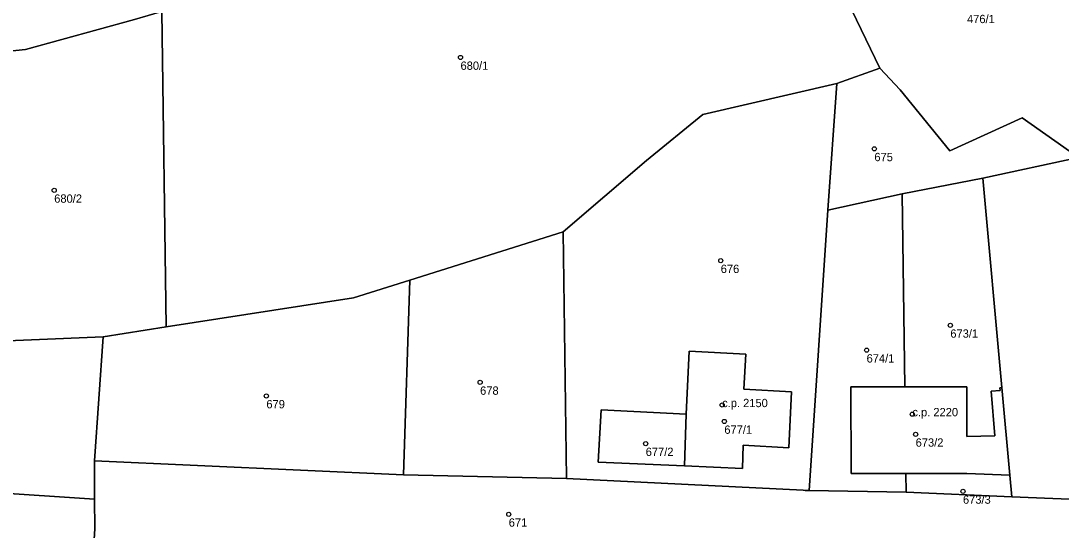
# Model space of a CAD drawing. Extents: x -878211 to -870363, y -1058464 to -1052522.
# Drawn here: x -874523.6 to -874398.3, y -1056486.9 to -1056425.6 of the extents above; entities that cross this region are included whole.
import ezdxf

# ---------------------------------------------------------------- set-up
doc = ezdxf.new("R2010")
doc.units = 0
for name, color, linetype in [('Definiční body', 7, 'Continuous'), ('Polygon budovy', 7, 'Continuous'), ('Polygon parcely', 7, 'Continuous')]:
    doc.layers.add(name, color=color, linetype=linetype)

msp = doc.modelspace()

# ---------------------------------------------------------------- linework, layer by layer
at = {"layer": 'Definiční body'}
for centre in [(-874470.63, -1056429.99994), (-874420.77, -1056440.99994), (-874519.58, -1056445.99994), (-874439.28, -1056454.45994), (-874411.62, -1056462.24994), (-874421.71, -1056465.23994), (-874468.27, -1056469.11994), (-874494.02, -1056470.74994), (-874439.11, -1056471.84994), (-874438.85, -1056473.81994), (-874416.19, -1056472.94994), (-874415.8, -1056475.36994), (-874448.32, -1056476.48994), (-874410.1, -1056482.23994), (-874464.82, -1056484.99994)]:
    msp.add_circle(centre, 0.25, dxfattribs=at)
at = {"layer": 'Polygon budovy'}
for points in [[(-874443.66, -1056479.17), (-874436.67, -1056479.47), (-874436.57, -1056476.69), (-874431.07, -1056476.98), (-874430.76, -1056470.25), (-874436.48, -1056469.95), (-874436.27, -1056465.74), (-874443.07, -1056465.36), (-874443.46, -1056472.94)], [(-874417.11, -1056469.65), (-874423.59, -1056469.65), (-874423.57, -1056480.1), (-874416.97, -1056480.09), (-874409.63, -1056480.07), (-874404.47, -1056480.3), (-874405.42, -1056469.74), (-874405.66, -1056469.79), (-874405.61, -1056470.08), (-874406.72, -1056470.18), (-874406.25, -1056475.54), (-874409.64, -1056475.64), (-874409.64, -1056469.65)]]:
    msp.add_lwpolyline(points, close=True, dxfattribs=at)
at = {"layer": 'Polygon parcely'}
for points in [[(-874480.73, -1056416.32), (-874482.07, -1056416.75), (-874490.03, -1056419.45), (-874505.5, -1056424.13), (-874506.63, -1056424.46), (-874506.09, -1056462.44), (-874483.53, -1056458.93), (-874476.75, -1056456.82), (-874458.26, -1056450.98), (-874448.21, -1056442.41), (-874441.44, -1056436.86), (-874425.29, -1056433.14), (-874420.12, -1056431.27), (-874435.23, -1056399.98), (-874439.22, -1056401.77), (-874464.13, -1056411.06)], [(-874506.63, -1056424.46), (-874505.5, -1056424.13), (-874490.03, -1056419.45), (-874482.07, -1056416.75), (-874480.73, -1056416.32), (-874484.53, -1056404.72), (-874506.28, -1056409.52), (-874544.06, -1056414.29), (-874571.8, -1056418.71), (-874569.39, -1056432.89), (-874561.56, -1056432.43), (-874554.89, -1056431.78), (-874547.93, -1056431.29), (-874538.64, -1056430.41), (-874535.46, -1056430.33), (-874523.03, -1056429.03), (-874509.91, -1056425.43)], [(-874509.91, -1056425.43), (-874523.03, -1056429.03), (-874535.46, -1056430.33), (-874537.69, -1056464.65), (-874513.7, -1056463.63), (-874506.09, -1056462.44), (-874506.63, -1056424.46)], [(-874417.41, -1056446.4), (-874407.71, -1056444.55), (-874396.18, -1056442.04), (-874402.98, -1056437.26), (-874411.69, -1056441.25), (-874417.67, -1056433.88), (-874420.12, -1056431.27), (-874425.29, -1056433.14), (-874426.38, -1056448.38)], [(-874457.88, -1056480.71), (-874429.37, -1056482.11), (-874429.12, -1056482.12), (-874428.61, -1056482.15), (-874426.38, -1056448.38), (-874425.29, -1056433.14), (-874441.44, -1056436.86), (-874448.21, -1056442.41), (-874458.26, -1056450.98)], [(-874404.47, -1056480.3), (-874404.23, -1056482.9), (-874370.58, -1056484.27), (-874393, -1056445.85), (-874396.18, -1056442.04), (-874407.71, -1056444.55), (-874405.42, -1056469.74)], [(-874407.71, -1056444.55), (-874417.41, -1056446.4), (-874417.11, -1056469.65), (-874409.64, -1056469.65), (-874409.64, -1056475.64), (-874406.25, -1056475.54), (-874406.72, -1056470.18), (-874405.61, -1056470.08), (-874405.66, -1056469.79), (-874405.42, -1056469.74)], [(-874417.11, -1056469.65), (-874417.41, -1056446.4), (-874426.38, -1056448.38), (-874428.61, -1056482.15), (-874416.94, -1056482.33), (-874416.97, -1056480.09), (-874423.57, -1056480.1), (-874423.59, -1056469.65)], [(-874477.5, -1056480.25), (-874457.88, -1056480.71), (-874458.26, -1056450.98), (-874476.75, -1056456.82)], [(-874514.72, -1056478.57), (-874477.5, -1056480.25), (-874476.75, -1056456.82), (-874483.53, -1056458.93), (-874506.09, -1056462.44), (-874513.7, -1056463.63)], [(-874514.71, -1056483.17), (-874514.72, -1056478.57), (-874513.7, -1056463.63), (-874537.69, -1056464.65), (-874540.74, -1056481.47)], [(-874443.46, -1056472.94), (-874443.07, -1056465.36), (-874436.27, -1056465.74), (-874436.48, -1056469.95), (-874430.76, -1056470.25), (-874431.07, -1056476.98), (-874436.57, -1056476.69), (-874436.67, -1056479.47), (-874443.66, -1056479.17), (-874454.05, -1056478.73), (-874453.7, -1056472.43)], [(-874443.46, -1056472.94), (-874443.66, -1056479.17), (-874436.67, -1056479.47), (-874436.57, -1056476.69), (-874431.07, -1056476.98), (-874430.76, -1056470.25), (-874436.48, -1056469.95), (-874436.27, -1056465.74), (-874443.07, -1056465.36)], [(-874416.97, -1056480.09), (-874409.63, -1056480.07), (-874404.47, -1056480.3), (-874405.42, -1056469.74), (-874405.66, -1056469.79), (-874405.61, -1056470.08), (-874406.72, -1056470.18), (-874406.25, -1056475.54), (-874409.64, -1056475.64), (-874409.64, -1056469.65), (-874417.11, -1056469.65), (-874423.59, -1056469.65), (-874423.57, -1056480.1)], [(-874443.46, -1056472.94), (-874453.7, -1056472.43), (-874454.05, -1056478.73), (-874443.66, -1056479.17)], [(-874416.94, -1056482.33), (-874404.23, -1056482.9), (-874404.47, -1056480.3), (-874409.63, -1056480.07), (-874416.97, -1056480.09)], [(-874540.74, -1056481.47), (-874541.04, -1056482.41), (-874536.01, -1056483.21), (-874537.05, -1056490.1), (-874536.06, -1056490.23), (-874523.64, -1056490.9), (-874525.53, -1056503.93), (-874520.11, -1056504.57), (-874519.11, -1056504.61), (-874515.7, -1056503.29), (-874514.7, -1056486.72), (-874514.71, -1056483.17)]]:
    msp.add_lwpolyline(points, close=True, dxfattribs=at)
for points in [[(-874435.23, -1056399.98), (-874420.12, -1056431.27), (-874417.67, -1056433.88), (-874411.69, -1056441.25), (-874402.98, -1056437.26), (-874396.18, -1056442.04), (-874393, -1056445.85), (-874370.58, -1056484.27), (-874355.24, -1056493.16), (-874347.2, -1056502.65), (-874344.62, -1056505.87), (-874336.73, -1056517.84), (-874326.2, -1056533.69), (-874326.13, -1056535.82), (-874319.45, -1056543.71), (-874311.18, -1056556.62)], [(-874370.58, -1056484.27), (-874404.23, -1056482.9), (-874416.94, -1056482.33), (-874428.61, -1056482.15), (-874429.12, -1056482.12), (-874429.37, -1056482.11), (-874457.88, -1056480.71), (-874477.5, -1056480.25), (-874514.72, -1056478.57), (-874514.71, -1056483.17), (-874514.7, -1056486.72), (-874515.7, -1056503.29)]]:
    msp.add_lwpolyline(points, dxfattribs=at)

# ---------------------------------------------------------------- texts
at = {"layer": 'Definiční body'}
for s, p in [('476/1', (-874409.61, -1056425.869)), ('680/1', (-874470.63, -1056431.489)), ('675', (-874420.77, -1056442.489)), ('680/2', (-874519.58, -1056447.489)), ('676', (-874439.28, -1056455.949)), ('673/1', (-874411.62, -1056463.739)), ('674/1', (-874421.71, -1056466.729)), ('678', (-874468.27, -1056470.609)), ('c.p. 2150', (-874439.11, -1056472.1)), ('679', (-874494.02, -1056472.239)), ('c.p. 2220', (-874416.19, -1056473.2)), ('677/1', (-874438.85, -1056475.309)), ('673/2', (-874415.8, -1056476.859)), ('677/2', (-874448.32, -1056477.979)), ('673/3', (-874410.1, -1056483.729)), ('671', (-874464.82, -1056486.489))]:
    msp.add_text(s, height=0.999996, dxfattribs=at).set_placement(p)

doc.saveas('drawing.dxf')
